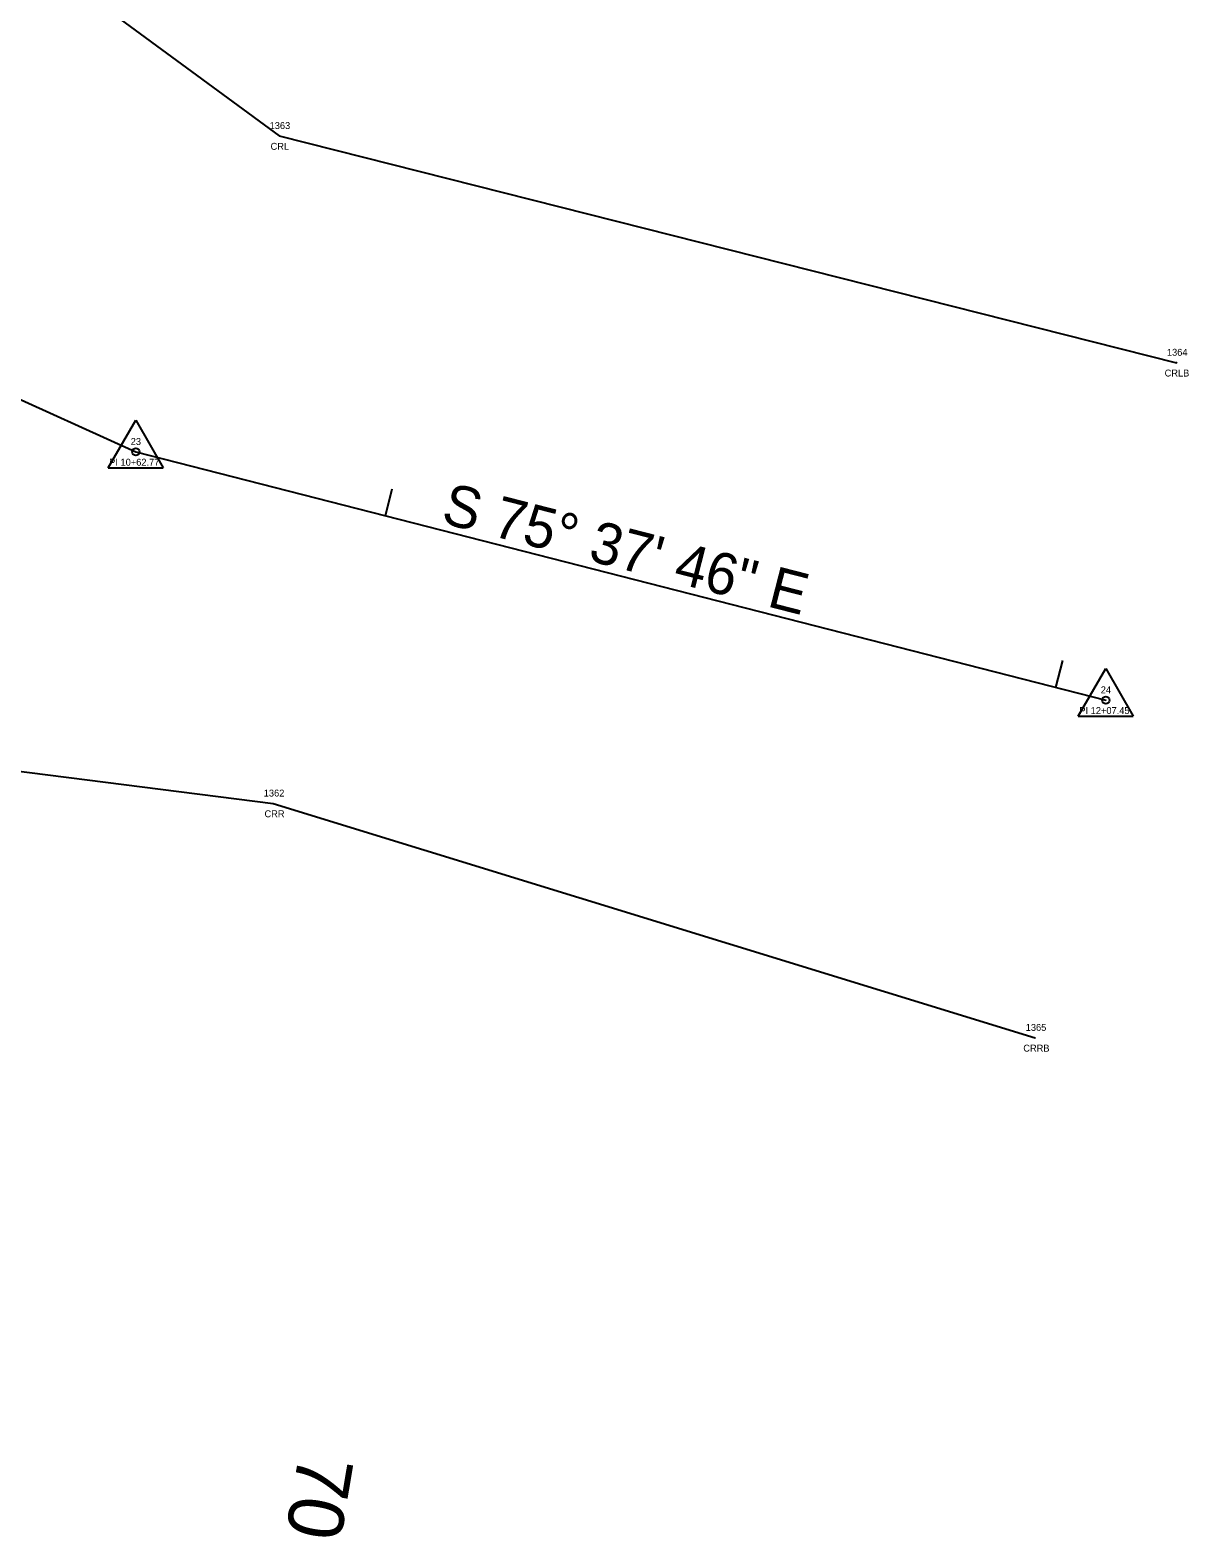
# Model space of a CAD drawing. Extents: x 2432632 to 2433497, y 684847 to 688233.
# Drawn here: x 2433169.5 to 2433336.9, y 685823.7 to 686041.7 of the extents above; entities that cross this region are included whole.
import ezdxf

# ---------------------------------------------------------------- set-up
doc = ezdxf.new("R2010")
doc.units = 0
for name, color, linetype in [('RD_EX_H2O', 7, 'Continuous'), ('RD_EX_H2O_txCode', 7, 'Continuous'), ('RD_HC_Cl', 7, 'Continuous'), ('RD_HC_Data', 7, 'Continuous'), ('RD_HC_Data_Tic', 7, 'Continuous'), ('RD_HC_TX_Sta50', 7, 'Continuous'), ('RD_HC_txCode', 7, 'Continuous'), ('RD_SMD_Locator', 7, 'Continuous')]:
    doc.layers.add(name, color=color, linetype=linetype)

msp = doc.modelspace()

# ---------------------------------------------------------------- linework, layer by layer
at = {"layer": 'RD_EX_H2O'}
for points in [[(2433007.74, 686209.38), (2433001.59, 686166.41), (2433024.46, 686126.62), (2433051.58, 686097.06), (2433120.95, 686072.12), (2433152.82, 686065.09), (2433205.51, 686026.38), (2433335.15, 685993.61)], [(2432923.04, 686077.65), (2433019.93, 685999.69), (2433090.75, 685956.18), (2433102.59, 685949.56), (2433131.31, 685944.06), (2433132.23, 685945.04), (2433164.1, 685935.07), (2433204.66, 685929.9), (2433314.75, 685896.03)]]:
    msp.add_lwpolyline(points, dxfattribs=at)
at = {"layer": 'RD_HC_Cl'}
for p, q in [((2433035.76, 686048.38), (2433184.8, 685980.72)), ((2433184.8, 685980.72), (2433324.95, 685944.82))]:
    msp.add_line(p, q, dxfattribs=at)
at = {"layer": 'RD_HC_Data'}
for p, q in [((2433180.83, 685978.43), (2433184.8, 685985.31)), ((2433184.8, 685985.31), (2433188.77, 685978.43)), ((2433180.83, 685978.43), (2433188.77, 685978.43)), ((2433320.98, 685942.52), (2433324.95, 685949.4)), ((2433324.95, 685949.4), (2433328.92, 685942.52)), ((2433320.98, 685942.52), (2433328.92, 685942.52))]:
    msp.add_line(p, q, dxfattribs=at)
for centre in [(2433184.8, 685980.72), (2433324.95, 685944.82)]:
    msp.add_circle(centre, 0.529, dxfattribs=at)
at = {"layer": 'RD_HC_Data_Tic'}
for p, q in [((2433220.87, 685971.48), (2433221.86, 685975.36)), ((2433317.74, 685946.67), (2433318.73, 685950.54))]:
    msp.add_line(p, q, dxfattribs=at)
at = {"layer": 'RD_SMD_Locator'}
for centre in [(2433205.51, 686026.38), (2433335.15, 685993.61), (2433184.8, 685980.72), (2433324.95, 685944.82), (2433204.66, 685929.9), (2433314.75, 685896.03)]:
    msp.add_circle(centre, 0.001, dxfattribs=at)

# ---------------------------------------------------------------- texts
at = {"layer": 'RD_EX_H2O_txCode'}
for s, p in [('1363', (2433204.14, 686027.38)), ('CRL', (2433204.28, 686024.38)), ('1364', (2433333.78, 685994.61)), ('CRLB', (2433333.45, 685991.61)), ('1362', (2433203.29, 685930.9)), ('CRR', (2433203.4, 685927.9)), ('1365', (2433313.38, 685897.03)), ('CRRB', (2433313.03, 685894.03))]:
    msp.add_text(s, height=1, dxfattribs=at).set_placement(p)
at = {"layer": 'RD_HC_Data'}
msp.add_text('S 75%%d 37\' 46" E', height=6, rotation=345.6295, dxfattribs=at).set_placement((2433228.73, 685970.5))
at = {"layer": 'RD_HC_TX_Sta50'}
msp.add_text('70', height=8, rotation=260.4335, dxfattribs=at).set_placement((2433208.41, 685836.07))
at = {"layer": 'RD_HC_txCode'}
for s, p in [('23', (2433184.07, 685981.72)), ('PI 10+62.77', (2433180.96, 685978.72)), ('24', (2433324.22, 685945.82)), ('PI 12+07.45', (2433321.13, 685942.82))]:
    msp.add_text(s, height=1, dxfattribs=at).set_placement(p)

doc.saveas('drawing.dxf')
